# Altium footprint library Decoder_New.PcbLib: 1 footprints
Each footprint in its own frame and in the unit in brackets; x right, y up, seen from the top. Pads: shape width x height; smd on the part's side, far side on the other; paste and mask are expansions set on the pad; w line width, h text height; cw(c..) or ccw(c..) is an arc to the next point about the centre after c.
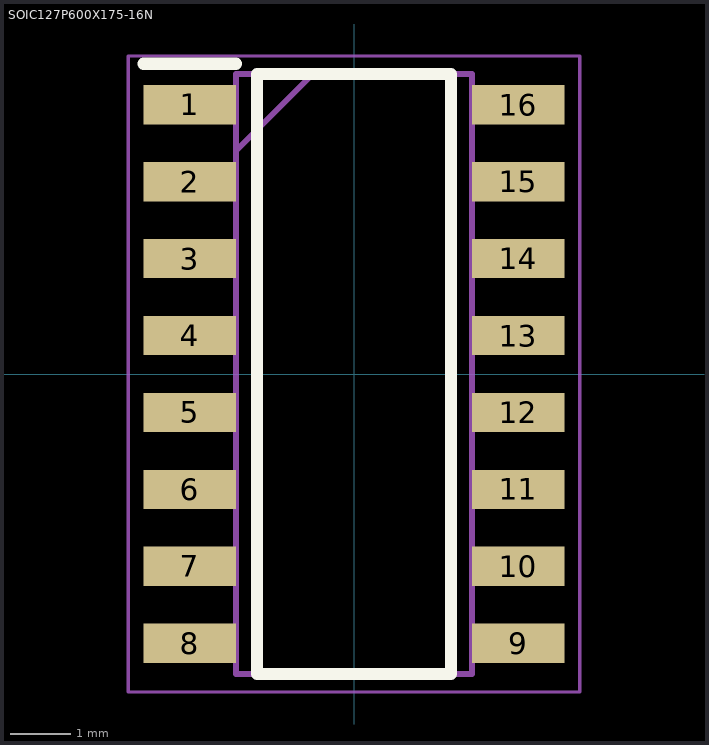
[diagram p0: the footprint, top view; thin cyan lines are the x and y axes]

## SOIC127P600X175-16N [mm]
pads (16):
  rect 1.525x0.65 smd: 1(-2.712,4.445) 2(-2.712,3.175) 3(-2.712,1.905) 4(-2.712,0.635) 5(-2.712,-0.635) 6(-2.712,-1.905) 7(-2.712,-3.175) 8(-2.712,-4.445) 9(2.712,-4.445) 10(2.712,-3.175) 11(2.712,-1.905) 12(2.712,-0.635) 13(2.712,0.635) 14(2.712,1.905) 15(2.712,3.175) 16(2.712,4.445)
Top Overlay:
  lines w0.2: -3.475,5.12 -1.95,5.12 ; -1.6,-4.95 1.6,-4.95 1.6,4.95 -1.6,4.95 -1.6,-4.95
Mechanical 13:
  lines w0.1: -1.95,3.68 -0.68,4.95 ; -1.95,-4.95 1.95,-4.95 1.95,4.95 -1.95,4.95 -1.95,-4.95
Mechanical 15:
  lines w0.05: -3.725,-5.25 3.725,-5.25 3.725,5.25 -3.725,5.25 -3.725,-5.25
3D body "SN74AHC138D.stp": height 1.75, standoff 0, extent -3,-4.95 3,4.95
